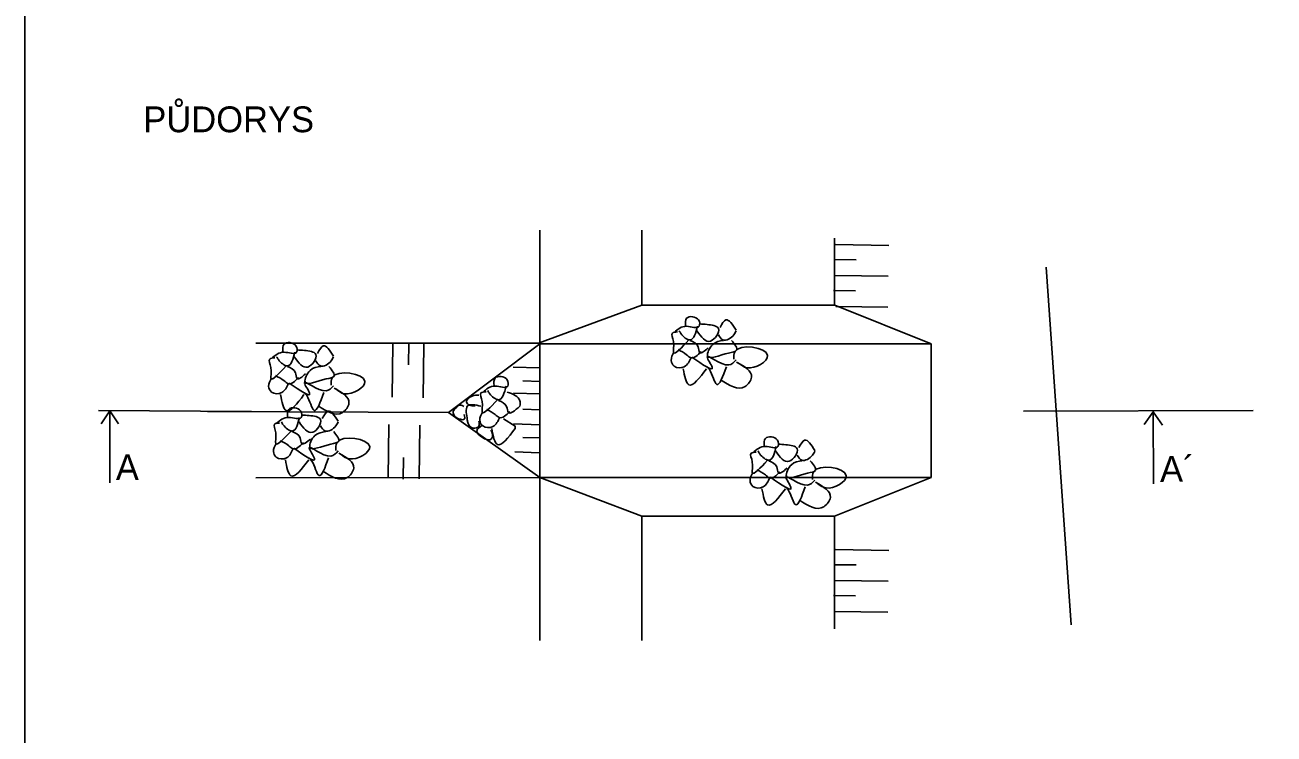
# Model space of a CAD drawing. Extents: x -463095.2 to -463015.6, y -1105044.4 to -1104976.7.
# Drawn here: x -463058.13 to -463032.2, y -1105006.18 to -1104991.46 of the extents above; entities that cross this region are included whole.
import ezdxf

# ---------------------------------------------------------------- set-up
doc = ezdxf.new("R2010")
doc.units = 0
doc.layers.add('Implicitní', color=7, linetype='Continuous')
doc.layers.add('Vrstva 14', color=7, linetype='Continuous')

msp = doc.modelspace()

# ---------------------------------------------------------------- linework, layer by layer
at = {"layer": 'Implicitní'}
msp.add_lwpolyline([(-463058.132, -1104977.232), (-463016.132, -1104977.232), (-463016.132, -1105036.632), (-463058.132, -1105036.632)], close=True, dxfattribs=at)
at = {"layer": 'Vrstva 14'}
for p, q in [((-463047.441, -1104995.719), (-463047.441, -1104998.079)), ((-463045.319, -1104995.719), (-463045.319, -1104997.29)), ((-463041.319, -1104995.887), (-463041.319, -1104997.281)), ((-463040.19, -1104996.034), (-463041.3, -1104996.018)), ((-463040.874, -1104996.336), (-463041.326, -1104996.33)), ((-463047.443, -1104996.574), (-463047.443, -1104998.233)), ((-463036.926, -1104996.487), (-463036.404, -1105003.917)), ((-463040.205, -1104996.675), (-463041.315, -1104996.659)), ((-463040.889, -1104996.977), (-463041.341, -1104996.971)), ((-463045.319, -1104997.278), (-463047.471, -1104998.064)), ((-463040.215, -1104997.317), (-463041.293, -1104997.302)), ((-463050.506, -1104999.187), (-463050.49, -1104998.069)), ((-463050.166, -1104998.513), (-463050.16, -1104998.061)), ((-463049.864, -1104999.197), (-463049.848, -1104998.087)), ((-463039.317, -1104998.079), (-463047.441, -1104998.079)), ((-463039.317, -1104998.079), (-463039.317, -1105000.857)), ((-463047.994, -1104998.563), (-463047.445, -1104998.578)), ((-463047.795, -1104998.849), (-463047.441, -1104998.858)), ((-463047.986, -1104999.1), (-463047.441, -1104999.116)), ((-463047.795, -1104999.436), (-463047.441, -1104999.446)), ((-463056.608, -1104999.464), (-463053.43, -1104999.486)), ((-463054.339, -1104999.483), (-463049.334, -1104999.506)), ((-463034.702, -1104999.488), (-463034.513, -1104999.767)), ((-463050.573, -1104999.756), (-463050.589, -1105000.866)), ((-463049.931, -1104999.766), (-463049.947, -1105000.884)), ((-463047.99, -1104999.743), (-463047.441, -1104999.758)), ((-463047.795, -1105000.024), (-463047.441, -1105000.033)), ((-463050.271, -1105000.44), (-463050.277, -1105000.892)), ((-463047.958, -1105000.324), (-463047.445, -1105000.339)), ((-463047.441, -1105000.857), (-463047.441, -1105004.241)), ((-463047.441, -1105000.857), (-463045.319, -1105001.657)), ((-463045.319, -1105001.659), (-463045.319, -1105004.241)), ((-463041.319, -1105001.66), (-463041.319, -1105003.995)), ((-463040.19, -1105002.369), (-463041.3, -1105002.353)), ((-463040.874, -1105002.671), (-463041.326, -1105002.665)), ((-463040.205, -1105003.01), (-463041.315, -1105002.994)), ((-463040.889, -1105003.312), (-463041.341, -1105003.306)), ((-463040.215, -1105003.652), (-463041.333, -1105003.636))]:
    msp.add_line(p, q, dxfattribs=at)
for points in [[(-463045.319, -1104997.278), (-463041.318, -1104997.278), (-463039.317, -1104998.079)], [(-463053.336, -1104998.064), (-463047.471, -1104998.064)], [(-463056.37, -1105000.962), (-463056.37, -1104999.467), (-463056.552, -1104999.74)], [(-463056.37, -1105000.962), (-463056.37, -1104999.467), (-463056.189, -1104999.74)], [(-463047.953, -1104999.838), (-463047.953, -1104999.788), (-463048.192, -1104999.637)], [(-463037.394, -1104999.477), (-463032.625, -1104999.466)], [(-463034.697, -1105000.984), (-463034.702, -1104999.488), (-463034.892, -1104999.755)], [(-463053.336, -1105000.86), (-463047.441, -1105000.857)], [(-463039.317, -1105000.857), (-463047.441, -1105000.857)], [(-463041.319, -1105001.657), (-463039.317, -1105000.857)], [(-463041.329, -1105001.657), (-463045.332, -1105001.657)]]:
    msp.add_lwpolyline(points, dxfattribs=at)
msp.add_lwpolyline([(-463047.441, -1105000.857), (-463049.334, -1104999.506), (-463047.441, -1104998.079)], close=True, dxfattribs=at)
for points in [[(-463044.652, -1104997.843), (-463044.392, -1104997.713), (-463044.132, -1104997.713), (-463044.144, -1104997.583), (-463044.392, -1104997.547), (-463044.416, -1104997.701)], [(-463043.696, -1104997.737), (-463043.578, -1104997.583), (-463043.366, -1104997.795)], [(-463044.346, -1104997.997), (-463044.664, -1104998.257), (-463044.664, -1104998.033), (-463044.688, -1104997.855), (-463044.582, -1104997.831)], [(-463044.168, -1104997.713), (-463044.322, -1104997.997), (-463044.51, -1104997.867), (-463044.546, -1104997.807)], [(-463044.18, -1104997.807), (-463043.896, -1104998.021), (-463043.732, -1104997.761), (-463043.968, -1104997.677), (-463044.122, -1104997.665)], [(-463043.732, -1104997.891), (-463043.638, -1104997.997), (-463043.414, -1104997.891), (-463043.366, -1104997.807)], [(-463053.012, -1104998.382), (-463052.752, -1104998.252), (-463052.492, -1104998.252), (-463052.504, -1104998.122), (-463052.752, -1104998.086), (-463052.776, -1104998.24)], [(-463052.056, -1104998.276), (-463051.938, -1104998.122), (-463051.726, -1104998.334)], [(-463043.944, -1104998.163), (-463044.122, -1104998.257), (-463044.156, -1104998.139), (-463044.322, -1104998.009)], [(-463043.46, -1104998.009), (-463043.354, -1104998.211), (-463043.52, -1104998.269), (-463043.956, -1104998.329), (-463043.85, -1104998.091), (-463043.626, -1104998.009)], [(-463043.414, -1104998.399), (-463043.394, -1104998.243), (-463042.712, -1104998.321), (-463043.14, -1104998.575), (-463043.316, -1104998.477)], [(-463052.706, -1104998.536), (-463053.024, -1104998.796), (-463053.024, -1104998.572), (-463053.048, -1104998.394), (-463052.942, -1104998.37)], [(-463052.528, -1104998.252), (-463052.682, -1104998.536), (-463052.87, -1104998.406), (-463052.906, -1104998.346)], [(-463052.54, -1104998.346), (-463052.256, -1104998.56), (-463052.092, -1104998.3), (-463052.328, -1104998.216), (-463052.482, -1104998.204)], [(-463052.092, -1104998.43), (-463051.998, -1104998.536), (-463051.774, -1104998.43), (-463051.726, -1104998.346)], [(-463044.3, -1104998.359), (-463044.44, -1104998.553), (-463044.652, -1104998.541), (-463044.712, -1104998.423), (-463044.654, -1104998.253)], [(-463044.09, -1104998.241), (-463044.31, -1104998.365), (-463044.392, -1104998.305), (-463044.57, -1104998.199)], [(-463044.286, -1104998.353), (-463043.862, -1104998.565), (-463043.968, -1104998.353), (-463043.52, -1104998.517), (-463043.366, -1104998.411)], [(-463052.304, -1104998.702), (-463052.482, -1104998.796), (-463052.516, -1104998.678), (-463052.682, -1104998.548)], [(-463051.82, -1104998.548), (-463051.714, -1104998.75), (-463051.88, -1104998.808), (-463052.316, -1104998.868), (-463052.21, -1104998.63), (-463051.986, -1104998.548)], [(-463051.774, -1104998.938), (-463051.754, -1104998.782), (-463051.072, -1104998.86), (-463051.5, -1104999.114), (-463051.676, -1104999.016)], [(-463043.978, -1104998.595), (-463044.348, -1104998.927), (-463044.464, -1104998.595)], [(-463043.566, -1104998.553), (-463043.768, -1104998.921), (-463043.92, -1104998.613), (-463043.968, -1104998.553)], [(-463043.354, -1104998.457), (-463043.044, -1104998.771), (-463043.18, -1104998.965), (-463043.686, -1104998.829)], [(-463052.66, -1104998.898), (-463052.8, -1104999.092), (-463053.012, -1104999.08), (-463053.072, -1104998.962), (-463053.014, -1104998.792)], [(-463052.45, -1104998.78), (-463052.67, -1104998.904), (-463052.752, -1104998.844), (-463052.93, -1104998.738)], [(-463052.646, -1104998.892), (-463052.222, -1104999.104), (-463052.328, -1104998.892), (-463051.88, -1104999.056), (-463051.726, -1104998.95)], [(-463048.627, -1104999.086), (-463048.367, -1104998.956), (-463048.107, -1104998.956), (-463048.119, -1104998.826), (-463048.367, -1104998.79), (-463048.391, -1104998.944)], [(-463052.338, -1104999.134), (-463052.708, -1104999.466), (-463052.824, -1104999.134)], [(-463051.926, -1104999.092), (-463052.128, -1104999.46), (-463052.28, -1104999.152), (-463052.328, -1104999.092)], [(-463051.714, -1104998.996), (-463051.404, -1104999.31), (-463051.54, -1104999.504), (-463052.046, -1104999.368)], [(-463048.707, -1104999.145), (-463048.847, -1104999.163), (-463048.964, -1104999.285), (-463048.909, -1104999.35), (-463048.786, -1104999.363)], [(-463048.321, -1104999.24), (-463048.639, -1104999.5), (-463048.639, -1104999.276), (-463048.663, -1104999.098), (-463048.557, -1104999.074)], [(-463048.143, -1104998.956), (-463048.297, -1104999.24), (-463048.485, -1104999.11), (-463048.521, -1104999.05)], [(-463047.854, -1104999.372), (-463047.854, -1104999.26), (-463048.118, -1104999.079)], [(-463052.913, -1104999.735), (-463052.653, -1104999.605), (-463052.393, -1104999.605), (-463052.405, -1104999.475), (-463052.653, -1104999.439), (-463052.677, -1104999.593)], [(-463051.957, -1104999.629), (-463051.839, -1104999.475), (-463051.627, -1104999.687)], [(-463049.018, -1104999.381), (-463049.093, -1104999.349), (-463049.192, -1104999.418), (-463049.238, -1104999.487), (-463049.211, -1104999.573), (-463049.09, -1104999.646), (-463049.009, -1104999.646), (-463049.009, -1104999.546)], [(-463048.663, -1104999.373), (-463048.946, -1104999.373), (-463048.946, -1104999.655), (-463048.93, -1104999.732), (-463048.827, -1104999.828), (-463048.707, -1104999.789), (-463048.707, -1104999.684)], [(-463048.065, -1104999.484), (-463048.285, -1104999.608), (-463048.367, -1104999.548), (-463048.545, -1104999.442)], [(-463047.854, -1104999.372), (-463048.097, -1104999.5), (-463048.131, -1104999.382), (-463048.297, -1104999.252)], [(-463052.429, -1104999.605), (-463052.583, -1104999.889), (-463052.771, -1104999.759), (-463052.807, -1104999.699)], [(-463052.441, -1104999.699), (-463052.157, -1104999.913), (-463051.993, -1104999.653), (-463052.229, -1104999.569), (-463052.383, -1104999.557)], [(-463051.993, -1104999.783), (-463051.899, -1104999.889), (-463051.675, -1104999.783), (-463051.627, -1104999.699)], [(-463048.275, -1104999.602), (-463048.415, -1104999.796), (-463048.627, -1104999.784), (-463048.687, -1104999.666), (-463048.629, -1104999.496)], [(-463052.607, -1104999.889), (-463052.925, -1105000.149), (-463052.925, -1104999.925), (-463052.949, -1104999.747), (-463052.843, -1104999.723)], [(-463052.205, -1105000.055), (-463052.383, -1105000.149), (-463052.417, -1105000.031), (-463052.583, -1104999.901)], [(-463051.721, -1104999.901), (-463051.615, -1105000.103), (-463051.781, -1105000.161), (-463052.217, -1105000.221), (-463052.111, -1104999.983), (-463051.887, -1104999.901)], [(-463051.675, -1105000.291), (-463051.655, -1105000.135), (-463050.973, -1105000.213), (-463051.401, -1105000.467), (-463051.577, -1105000.369)], [(-463048.653, -1104999.781), (-463048.745, -1104999.867), (-463048.498, -1105000.074), (-463048.477, -1105000.074), (-463048.438, -1104999.909), (-463048.466, -1104999.88)], [(-463047.953, -1104999.838), (-463048.323, -1105000.17), (-463048.439, -1104999.838)], [(-463052.561, -1105000.251), (-463052.701, -1105000.445), (-463052.913, -1105000.433), (-463052.973, -1105000.315), (-463052.915, -1105000.145)], [(-463052.351, -1105000.133), (-463052.571, -1105000.257), (-463052.653, -1105000.197), (-463052.831, -1105000.091)], [(-463052.547, -1105000.245), (-463052.123, -1105000.457), (-463052.229, -1105000.245), (-463051.781, -1105000.409), (-463051.627, -1105000.303)], [(-463043.016, -1105000.34), (-463042.756, -1105000.21), (-463042.496, -1105000.21), (-463042.508, -1105000.08), (-463042.756, -1105000.044), (-463042.78, -1105000.198)], [(-463042.532, -1105000.21), (-463042.686, -1105000.494), (-463042.874, -1105000.364), (-463042.91, -1105000.304)], [(-463042.544, -1105000.304), (-463042.26, -1105000.518), (-463042.096, -1105000.258), (-463042.332, -1105000.174), (-463042.486, -1105000.162)], [(-463042.06, -1105000.234), (-463041.942, -1105000.08), (-463041.73, -1105000.292)], [(-463052.239, -1105000.487), (-463052.609, -1105000.819), (-463052.725, -1105000.487)], [(-463051.827, -1105000.445), (-463052.029, -1105000.813), (-463052.181, -1105000.505), (-463052.229, -1105000.445)], [(-463051.615, -1105000.349), (-463051.305, -1105000.663), (-463051.441, -1105000.857), (-463051.947, -1105000.721)], [(-463042.71, -1105000.494), (-463043.028, -1105000.754), (-463043.028, -1105000.53), (-463043.052, -1105000.352), (-463042.946, -1105000.328)], [(-463042.096, -1105000.388), (-463042.002, -1105000.494), (-463041.778, -1105000.388), (-463041.73, -1105000.304)], [(-463042.664, -1105000.856), (-463042.804, -1105001.05), (-463043.016, -1105001.038), (-463043.076, -1105000.92), (-463043.018, -1105000.75)], [(-463042.454, -1105000.738), (-463042.674, -1105000.862), (-463042.756, -1105000.802), (-463042.934, -1105000.696)], [(-463042.308, -1105000.66), (-463042.486, -1105000.754), (-463042.52, -1105000.636), (-463042.686, -1105000.506)], [(-463041.824, -1105000.506), (-463041.718, -1105000.708), (-463041.884, -1105000.766), (-463042.32, -1105000.826), (-463042.214, -1105000.588), (-463041.99, -1105000.506)], [(-463041.778, -1105000.896), (-463041.758, -1105000.74), (-463041.076, -1105000.818), (-463041.504, -1105001.072), (-463041.68, -1105000.974)], [(-463042.65, -1105000.85), (-463042.226, -1105001.062), (-463042.332, -1105000.85), (-463041.884, -1105001.014), (-463041.73, -1105000.908)], [(-463041.718, -1105000.954), (-463041.408, -1105001.268), (-463041.544, -1105001.462), (-463042.05, -1105001.326)], [(-463042.342, -1105001.092), (-463042.712, -1105001.424), (-463042.828, -1105001.092)], [(-463041.93, -1105001.05), (-463042.132, -1105001.418), (-463042.284, -1105001.11), (-463042.332, -1105001.05)]]:
    msp.add_spline(points, degree=3, dxfattribs=at)

# ---------------------------------------------------------------- texts
for s, p in [('PŮDORYS', (-463055.674, -1104993.684)), ('A', (-463056.244, -1105000.908))]:
    msp.add_text(s, height=0.536, dxfattribs=at).set_placement(p)
msp.add_text('A´', height=0.536, rotation=0.2805, dxfattribs=at).set_placement((-463034.561, -1105000.945))

doc.saveas('drawing.dxf')
